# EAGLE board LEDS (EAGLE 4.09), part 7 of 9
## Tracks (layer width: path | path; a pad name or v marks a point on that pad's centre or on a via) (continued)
N$X.2554  (via drill 0.2)  (1 unrouted) (continued)
  other vias: 80.3,19.86
N$X.2555  (via drill 0.2)  (1 unrouted)
  Bottom 0.2: 80.62,22.52 80.08,23.07 79.72,23.07
  other vias: 80.58,22.5
N$X.2556  (via drill 0.2)  (1 unrouted)
  Bottom 0.2: 80.62,25.09 80.08,25.64 79.72,25.64
  other vias: 80.58,25.07
N$X.2557  (via drill 0.2)  (1 unrouted)
  Bottom 0.2: 82.31,25.09 81.77,25.64 81.42,25.64
  other vias: 82.27,25.07
N$X.2558  (via drill 0.2)  (1 unrouted)
  Bottom 0.2: 82.25,22.52 81.7,23.07 81.35,23.07
  other vias: 82.24,22.48
N$X.2559  (via drill 0.2)  (1 unrouted)
  Bottom 0.2: 82.11,19.91 81.56,20.45 81.22,20.45
  other vias: 82.06,19.89
N$X.2560  (via drill 0.2)  (1 unrouted)
  Bottom 0.2: 83.99,19.93 83.44,20.47 83.09,20.47
  other vias: 83.94,19.91
N$X.2561  (via drill 0.2)  (1 unrouted)
  Bottom 0.2: 84.03,22.55 83.49,23.09 83.14,23.09
  other vias: 83.99,22.53
N$X.2562  (via drill 0.2)  (1 unrouted)
  Bottom 0.2: 84.03,25.09 83.49,25.64 83.14,25.64
  other vias: 83.99,25.07
N$X.2563  (via drill 0.2)  (1 unrouted)
  Bottom 0.2: 85.83,25.12 85.28,25.66 84.93,25.66
  other vias: 85.78,25.1
N$X.2564  (via drill 0.2)  (1 unrouted)
  Bottom 0.2: 85.83,22.52 85.28,23.07 84.93,23.07
  other vias: 85.78,22.5
N$X.2565  (via drill 0.2)  (1 unrouted)
  Bottom 0.2: 85.83,19.88 85.28,20.43 84.93,20.43
  other vias: 85.78,19.86
N$X.2566  (via drill 0.2)  (1 unrouted)
  Bottom 0.2: 101.57,22.52 101.03,23.07 100.67,23.07
  other vias: 101.53,22.5
N$X.2567  (via drill 0.2)  (1 unrouted)
  Bottom 0.2: 101.59,19.95 101.05,20.5 100.7,20.5
  other vias: 101.55,19.89
N$X.2568  (via drill 0.2)  (1 unrouted)
  Bottom 0.2: 99.89,19.88 99.35,20.43 99,20.43
  other vias: 99.85,19.86
N$X.2569  (via drill 0.2)  (1 unrouted)
  Bottom 0.2: 99.88,22.5 99.33,23.04 98.98,23.04
  other vias: 99.83,22.48
N$X.2570  (via drill 0.2)  (1 unrouted)
  Bottom 0.2: 99.78,25.14 99.23,25.68 98.89,25.68
  other vias: 99.73,25.12
N$X.2571  (via drill 0.2)  (1 unrouted)
  Bottom 0.2: 98.06,25.16 97.52,25.71 97.16,25.71
  other vias: 98.02,25.1
N$X.2572  (via drill 0.2)  (1 unrouted)
  Bottom 0.2: 98.08,22.5 97.54,23.04 97.19,23.04
  other vias: 98.04,22.48
N$X.2573  (via drill 0.2)  (1 unrouted)
  Bottom 0.2: 98.03,19.88 97.49,20.43 97.14,20.43
  other vias: 97.99,19.86
N$X.2574  (via drill 0.2)  (1 unrouted)
  Bottom 0.2: 96.34,19.88 95.8,20.43 95.44,20.43
  other vias: 96.3,19.86
N$X.2575  (via drill 0.2)  (1 unrouted)
  Bottom 0.2: 96.36,22.5 95.81,23.04 95.47,23.04
  other vias: 96.31,22.48
N$X.2576  (via drill 0.2)  (1 unrouted)
  Bottom 0.2: 96.36,25.12 95.81,25.66 95.47,25.66
  other vias: 96.31,25.1
N$X.2577  (via drill 0.2)  (1 unrouted)
  Bottom 0.2: 94.61,25.07 94.07,25.62 93.72,25.62
  other vias: 94.57,25.05
N$X.2578  (via drill 0.2)  (1 unrouted)
  Bottom 0.2: 94.66,22.45 94.12,23 93.77,23
  other vias: 94.62,22.43
N$X.2579  (via drill 0.2)  (1 unrouted)
  Bottom 0.2: 94.69,19.84 94.14,20.38 93.79,20.38
  other vias: 94.56,19.88
N$X.2580  (via drill 0.2)  (1 unrouted)
  Bottom 0.2: 92.97,19.91 92.42,20.45 92.07,20.45
  other vias: 92.92,19.89
N$X.2581  (via drill 0.2)  (1 unrouted)
  Bottom 0.2: 92.97,22.5 92.42,23.04 92.07,23.04
  other vias: 92.92,22.48
N$X.2582  (via drill 0.2)  (1 unrouted)
  Bottom 0.2: 92.94,25.07 92.39,25.62 92.05,25.62
  other vias: 92.89,25.05
N$X.2583  (via drill 0.2)  (1 unrouted)
  Bottom 0.2: 91.15,25.09 90.61,25.64 90.25,25.64
  other vias: 91.11,25.07
N$X.2584  (via drill 0.2)  (1 unrouted)
  Bottom 0.2: 91.11,22.43 90.56,22.98 90.21,22.98
  other vias: 91.04,22.45
N$X.2585  (via drill 0.2)  (1 unrouted)
  Bottom 0.2: 91.15,19.88 90.61,20.43 90.25,20.43
  other vias: 91.11,19.86
N$X.2586  (via drill 0.2)  (1 unrouted)
  Bottom 0.2: 89.34,25.12 88.8,25.66 88.44,25.66
  other vias: 89.3,25.1
N$X.2587
  Bottom 0.2: 88.8,25.66 88.44,25.66
N$X.2588  (via drill 0.2)  (1 unrouted)
  Bottom 0.2: 87.59,25.05 87.05,25.59 86.7,25.59
  other vias: 87.53,25.09
N$X.2589  (via drill 0.2)  (1 unrouted)
  Bottom 0.2: 87.57,22.45 87.03,23 86.67,23
  other vias: 87.48,22.47
N$X.2590  (via drill 0.2)  (1 unrouted)
  Bottom 0.2: 89.3,22.48 88.75,23.02 88.4,23.02
  other vias: 89.25,22.46
N$X.2591  (via drill 0.2)  (1 unrouted)
  Bottom 0.2: 89.39,19.84 88.84,20.38 88.49,20.38
  other vias: 89.3,19.88
N$X.2592  (via drill 0.2)  (1 unrouted)
  Bottom 0.2: 87.62,19.91 87.08,20.45 86.72,20.45
  other vias: 87.58,19.89
N$X.2596  (via drill 0.2)  (1 unrouted)
  Bottom 0.2: 112.11,43.66 111.56,44.2 111.21,44.2
  other vias: 112.02,43.66
N$X.2597  (via drill 0.2)  (1 unrouted)
  Bottom 0.2: 112.02,41.13 111.47,41.68 111.12,41.68
  other vias: 111.97,41.11
N$X.2598  (via drill 0.2)  (1 unrouted)
  Bottom 0.2: 5.32,48.8 4.77,49.34 4.42,49.34
  other vias: 5.28,48.74
N$X.2599  (via drill 0.2)  (1 unrouted)
  Bottom 0.2: 7.06,48.8 6.52,49.34 6.17,49.34
  other vias: 7.02,48.75
N$X.2600  (via drill 0.2)  (1 unrouted)
  Bottom 0.2: 8.9,48.8 8.36,49.34 8.01,49.34
  other vias: 8.86,48.78
N$X.2601  (via drill 0.2)  (1 unrouted)
  Bottom 0.2: 10.67,48.75 10.12,49.3 9.77,49.3
  other vias: 10.62,48.73
N$X.2602  (via drill 0.2)  (1 unrouted)
  Bottom 0.2: 12.44,48.78 11.89,49.32 11.54,49.32
  other vias: 12.39,48.76
N$X.2603  (via drill 0.2)  (1 unrouted)
  Bottom 0.2: 14.18,48.82 13.63,49.37 13.29,49.37
  other vias: 14.13,48.8
N$X.2604  (via drill 0.2)  (1 unrouted)
  Bottom 0.2: 15.95,48.75 15.4,49.3 15.05,49.3
  other vias: 16.02,48.72
N$X.2605  (via drill 0.2)  (1 unrouted)
  Bottom 0.2: 17.59,48.75 17.05,49.3 16.7,49.3
  other vias: 17.81,48.76
N$X.2606  (via drill 0.2)  (1 unrouted)
  Bottom 0.2: 19.38,48.85 18.84,49.39 18.49,49.39
  other vias: 19.61,48.77
N$X.2607  (via drill 0.2)  (1 unrouted)
  Bottom 0.2: 21.06,48.78 20.52,49.32 20.17,49.32
  other vias: 21.41,48.76
N$X.2608  (via drill 0.2)  (1 unrouted)
  Bottom 0.2: 21.08,51.35 20.54,51.89 20.19,51.89
  other vias: 21.37,51.29
N$X.2609  (via drill 0.2)  (1 unrouted)
  Bottom 0.2: 19.34,51.35 18.79,51.89 18.45,51.89
  other vias: 19.57,51.29
N$X.2610  (via drill 0.2)  (1 unrouted)
  Bottom 0.2: 17.59,51.42 17.05,51.96 16.7,51.96
  other vias: 17.77,51.32
N$X.2611  (via drill 0.2)  (1 unrouted)
  Bottom 0.2: 15.83,51.39 15.29,51.94 14.94,51.94
  other vias: 16.03,51.31
N$X.2612  (via drill 0.2)  (1 unrouted)
  Bottom 0.2: 14.13,51.39 13.59,51.94 13.24,51.94
  other vias: 14.09,51.37
N$X.2613  (via drill 0.2)  (1 unrouted)
  Bottom 0.2: 12.34,51.42 11.79,51.96 11.45,51.96
  other vias: 12.29,51.4
N$X.2614  (via drill 0.2)  (1 unrouted)
  Bottom 0.2: 10.55,51.44 10.01,51.98 9.66,51.98
  other vias: 10.53,51.38
N$X.2615  (via drill 0.2)  (1 unrouted)
  Bottom 0.2: 8.86,51.32 8.31,51.87 7.96,51.87
  other vias: 8.81,51.3
N$X.2616  (via drill 0.2)  (1 unrouted)
  Bottom 0.2: 7.08,51.42 6.54,51.96 6.19,51.96
  other vias: 7.03,51.33
N$X.2617  (via drill 0.2)  (1 unrouted)
  Bottom 0.2: 5.26,51.37 4.72,51.92 4.51,51.94
  other vias: 5.24,51.31
N$X.2618  (via drill 0.2)  (1 unrouted)
  Bottom 0.2: 3.55,51.37 3.01,51.92 2.66,51.92
  other vias: 3.47,51.3
N$X.2619  (via drill 0.2)  (1 unrouted)
  Bottom 0.2: 3.58,53.96 3.03,54.51 2.68,54.51
  other vias: 3.52,53.91
N$X.2620  (via drill 0.2)  (1 unrouted)
  Bottom 0.2: 5.34,53.92 4.79,54.46 4.44,54.46
  other vias: 5.29,53.9
N$X.2621  (via drill 0.2)  (1 unrouted)
  Bottom 0.2: 7.04,53.96 6.5,54.51 6.14,54.51
  other vias: 7.05,53.92
N$X.2622  (via drill 0.2)  (1 unrouted)
  Bottom 0.2: 8.78,53.97 8.23,54.51 8.01,54.55
  other vias: 8.79,53.92
N$X.2623  (via drill 0.2)  (1 unrouted)
  Bottom 0.2: 10.6,53.96 10.06,54.51 9.71,54.51
  other vias: 10.57,53.89
N$X.2624  (via drill 0.2)  (1 unrouted)
  Bottom 0.2: 12.39,53.94 11.85,54.49 11.5,54.49
  other vias: 12.35,53.92
N$X.2625  (via drill 0.2)  (1 unrouted)
  Bottom 0.2: 14.13,53.96 13.59,54.51 13.24,54.51
  other vias: 14.09,53.94
N$X.2626  (via drill 0.2)  (1 unrouted)
  Bottom 0.2: 15.73,53.92 15.19,54.47 14.98,54.51
  other vias: 15.85,53.92
N$X.2627  (via drill 0.2)  (1 unrouted)
  Bottom 0.2: 17.55,54.01 17,54.55 16.65,54.55
  other vias: 17.7,53.89
N$X.2628  (via drill 0.2)  (1 unrouted)
  Bottom 0.2: 19.38,53.96 18.84,54.51 18.49,54.51
  other vias: 19.45,53.87
N$X.2629  (via drill 0.2)  (1 unrouted)
  Bottom 0.2: 21.38,53.87 20.52,54.55 20.17,54.55
  other vias: 21.35,53.88
N$X.2630  (via drill 0.2)  (1 unrouted)
  Bottom 0.2: 21.11,56.67 20.56,57.22 20.21,57.22
  other vias: 21.06,56.65
N$X.2631  (via drill 0.2)  (1 unrouted)
  Bottom 0.2: 19.46,56.72 18.95,57.26 18.61,57.26
  other vias: 19.56,56.63
N$X.2632  (via drill 0.2)  (1 unrouted)
  Bottom 0.2: 17.7,56.8 17.21,57.26 16.86,57.26
  other vias: 17.84,56.64
N$X.2633  (via drill 0.2)  (1 unrouted)
  Bottom 0.2: 15.97,56.72 15.43,57.26 15.08,57.26
  other vias: 16.05,56.62
N$X.2634  (via drill 0.2)  (1 unrouted)
  Bottom 0.2: 14.09,56.76 13.54,57.31 13.19,57.31
  other vias: 14.08,56.66
N$X.2635  (via drill 0.2)  (1 unrouted)
  Bottom 0.2: 12.32,56.72 11.78,57.26 11.43,57.26
  other vias: 12.42,56.68
N$X.2636  (via drill 0.2)  (1 unrouted)
  Bottom 0.2: 10.53,56.67 9.99,57.22 9.63,57.22
  other vias: 10.6,56.64
N$X.2637  (via drill 0.2)  (1 unrouted)
  Bottom 0.2: 8.74,56.69 8.2,57.24 7.84,57.24
  other vias: 8.77,56.63
N$X.2638  (via drill 0.2)  (1 unrouted)
  Bottom 0.2: 7,56.67 6.45,57.22 6.1,57.22
  other vias: 7.04,56.64
N$X.2639  (via drill 0.2)  (1 unrouted)
  Bottom 0.2: 5.25,56.65 4.71,57.19 4.35,57.19
  other vias: 5.21,56.63
N$X.2640  (via drill 0.2)  (1 unrouted)
  Bottom 0.2: 3.44,56.65 2.89,57.19 2.54,57.19
  other vias: 3.39,56.63
N$X.2641  (via drill 0.2)  (1 unrouted)
  Bottom 0.2: 21.2,59.43 20.65,59.97 20.3,59.97
  other vias: 21.39,59.35
N$X.2642  (via drill 0.2)  (1 unrouted)
  Bottom 0.2: 23.17,59.43 22.4,59.95 22.05,59.95
  other vias: 23.25,59.37
N$X.2643  (via drill 0.2)  (1 unrouted)
  Bottom 0.2: 22.95,56.65 22.4,57.19 22.05,57.19
  other vias: 22.9,56.63
N$X.2644  (via drill 0.2)  (1 unrouted)
  Bottom 0.2: 23.2,53.92 22.26,54.53 21.91,54.53
  other vias: 23.24,53.9
N$X.2645  (via drill 0.2)  (1 unrouted)
  Bottom 0.2: 22.86,51.39 22.31,51.94 21.96,51.94
  other vias: 22.81,51.37
N$X.2646  (via drill 0.2)  (1 unrouted)
  Bottom 0.2: 23.16,48.74 22.33,49.37 21.98,49.37
  other vias: 23.18,48.73
N$X.2647  (via drill 0.2)  (1 unrouted)
  Bottom 0.2: 24.95,48.74 24.1,49.39 23.75,49.39
  other vias: 24.97,48.73
N$X.2648  (via drill 0.2)  (1 unrouted)
  Bottom 0.2: 24.89,51.33 24.07,51.96 23.72,51.96
  other vias: 24.94,51.27
N$X.2649  (via drill 0.2)  (1 unrouted)
  Bottom 0.2: 25.06,53.88 24.05,54.51 23.7,54.51
  other vias: 25.03,53.91
N$X.2650  (via drill 0.2)  (1 unrouted)
  Bottom 0.2: 24.95,56.61 24.41,57.16 23.79,57.19
  other vias: 24.97,56.64
N$X.2651  (via drill 0.2)  (1 unrouted)
  Bottom 0.2: 24.98,59.39 24.12,59.97 23.77,59.97
  other vias: 25.01,59.39
N$X.2652  (via drill 0.2)  (1 unrouted)
  Bottom 0.2: 26.74,59.39 25.89,59.97 25.54,59.97
  other vias: 26.77,59.39
N$X.2653  (via drill 0.2)  (1 unrouted)
  Bottom 0.2: 26.79,56.64 25.95,57.24 25.61,57.24
  other vias: 26.77,56.65
N$X.2654  (via drill 0.2)  (1 unrouted)
  Bottom 0.2: 26.77,53.93 25.77,54.53 25.42,54.53
  other vias: 26.81,53.92
N$X.2655  (via drill 0.2)  (1 unrouted)
  Bottom 0.2: 26.81,51.32 25.7,51.92 25.68,51.94
  other vias: 26.82,51.31
N$X.2656  (via drill 0.2)  (1 unrouted)
  Bottom 0.2: 26.74,48.71 25.77,49.34 25.42,49.34
  other vias: 26.76,48.73
N$X.2657  (via drill 0.2)  (1 unrouted)
  Bottom 0.2: 28.57,48.74 27.56,49.34 27.21,49.34
  other vias: 28.59,48.74
N$X.2658  (via drill 0.2)  (2 unrouted)
  Bottom 0.2: 27.56,51.94 27.21,51.94 | 28.55,51.23 27.74,52.04 27.54,52.04
  other vias: 28.61,51.29
N$X.2659  (via drill 0.2)  (1 unrouted)
  Bottom 0.2: 28.66,53.9 27.54,54.51 27.19,54.51
  other vias: 28.62,53.91
N$X.2660  (via drill 0.2)  (1 unrouted)
  Bottom 0.2: 28.55,56.63 27.9,57.29 27.72,57.29
  other vias: 28.58,56.63
N$X.2661  (via drill 0.2)  (1 unrouted)
  Bottom 0.2: 28.52,59.39 27.61,59.97 27.26,59.97
  other vias: 28.59,59.36
N$X.2662  (via drill 0.2)  (1 unrouted)
  Bottom 0.2: 30.36,59.38 29.82,59.93 29.05,59.99
  other vias: 30.38,59.36
N$X.2663  (via drill 0.2)  (1 unrouted)
  Bottom 0.2: v30.4,56.63 29.81,57.22 29.52,57.22
N$X.2664  (via drill 0.2)  (2 unrouted)
  Bottom 0.2: 29.33,54.53 28.98,54.53 | 30.35,53.97 29.67,54.65 29.34,54.65
  other vias: 30.38,53.92
N$X.2665  (via drill 0.2)  (2 unrouted)
  Bottom 0.2: 29.36,51.94 29,51.94 | 30.4,51.3 29.8,51.89 29.43,51.89
  other vias: 30.43,51.34
N$X.2666  (via drill 0.2)  (1 unrouted)
  Bottom 0.2: 30.3,48.71 29.31,49.34 28.96,49.34
  other vias: 30.24,48.76
N$X.2667  (via drill 0.2)  (1 unrouted)
  Bottom 0.2: 32.18,48.75 31.47,49.45 31.17,49.45
  other vias: 32.21,48.76
N$X.2668  (via drill 0.2)  (1 unrouted)
  Bottom 0.2: 32.24,51.3 31.63,51.91 31.17,51.91
  other vias: 32.21,51.28
N$X.2669  (via drill 0.2)  (1 unrouted)
  Bottom 0.2: 32.24,53.78 31.45,54.57 31.28,54.57
  other vias: 32.21,53.92
N$X.2670  (via drill 0.2)  (1 unrouted)
  Bottom 0.2: 32.15,56.63 31.43,57.35 31.19,57.35
  other vias: 32.17,56.65
N$X.2671  (via drill 0.2)  (1 unrouted)
  Bottom 0.2: 32.13,59.42 31.58,59.97 30.79,59.99
  other vias: 32.19,59.36
N$X.2672  (via drill 0.2)  (1 unrouted)
  Bottom 0.2: 33.98,59.33 33.44,59.88 33.06,59.88
  other vias: 33.98,59.36
N$X.2673  (via drill 0.2)  (1 unrouted)
  Bottom 0.2: 34,56.63 33.36,57.27 32.97,57.27
  other vias: 34.03,56.63
N$X.2674  (via drill 0.2)  (1 unrouted)
  Bottom 0.2: 34.13,53.93 33.56,54.5 32.94,54.5
  other vias: 34.06,53.95
N$X.2675  (via drill 0.2)  (1 unrouted)
  Bottom 0.2: 34,51.27 33.49,51.78 32.97,51.78
  other vias: 33.98,51.33
N$X.2676  (via drill 0.2)  (1 unrouted)
  Bottom 0.2: 33.95,48.75 33.34,49.37 33.12,49.37
  other vias: 34.02,48.76
N$X.2677  (via drill 0.2)  (1 unrouted)
  Bottom 0.2: 35.82,48.73 35.18,49.37 34.48,49.37
  other vias: 35.78,48.76
N$X.2678  (via drill 0.2)  (1 unrouted)
  Bottom 0.2: 35.77,51.27 35.05,52 34.68,52
  other vias: 35.79,51.33
N$X.2679  (via drill 0.2)  (1 unrouted)
  Bottom 0.2: 35.84,53.89 35.25,54.48 34.83,54.48
  other vias: 35.8,53.94
N$X.2680  (via drill 0.2)  (1 unrouted)
  Bottom 0.2: 35.8,56.67 35.27,57.2 34.9,57.2
  other vias: 35.81,56.65
N$X.2681  (via drill 0.2)  (1 unrouted)
  Bottom 0.2: 35.75,59.34 35.2,59.88 34.81,59.95
  other vias: 35.74,59.36
N$X.2682  (via drill 0.2)  (1 unrouted)
  Bottom 0.2: 37.6,59.41 37.06,59.95 36.44,59.95
  other vias: 37.65,59.36
N$X.2683  (via drill 0.2)  (1 unrouted)
  Bottom 0.2: v37.62,56.61 37.03,57.2 36.63,57.2
N$X.2684  (via drill 0.2)  (1 unrouted)
  Bottom 0.2: 37.69,53.93 37.03,54.59 36.43,54.59
  other vias: 37.64,53.9
N$X.2685  (via drill 0.2)  (1 unrouted)
  Bottom 0.2: v37.64,51.34 36.98,52 36.52,52
N$X.2686  (via drill 0.2)  (1 unrouted)
  Bottom 0.2: 37.64,48.77 37,49.41 36.56,49.41
  other vias: 37.64,48.75
N$X.2687  (via drill 0.2)  (1 unrouted)
  Bottom 0.2: 39.46,48.73 38.87,49.32 38.34,49.32
  other vias: 39.45,48.73
N$X.2688  (via drill 0.2)  (1 unrouted)
  Bottom 0.2: 39.4,51.27 38.69,51.98 38.25,51.98
  other vias: 39.38,51.33
N$X.2689  (via drill 0.2)  (1 unrouted)
  Bottom 0.2: 39.42,53.91 38.89,54.44 38.39,54.44
  other vias: 39.43,53.9
N$X.2690  (via drill 0.2)  (1 unrouted)
  Bottom 0.2: 39.44,56.67 38.85,57.27 38.52,57.27
  other vias: 39.39,56.65
N$X.2691  (via drill 0.2)  (1 unrouted)
  Bottom 0.2: 39.44,59.31 38.89,59.86 38.41,59.94
  other vias: 39.46,59.34
N$X.2753
  Bottom 0.2: 60.63,51.87 60.28,51.87
N$X.2755
  Bottom 0.2: 62.38,54.53 62.03,54.53
N$X.2756
  Bottom 0.2: 62.34,51.89 61.98,51.89
N$X.2757
  Bottom 0.2: 62.45,49.25 62.09,49.25
N$X.2758
  Bottom 0.2: 64.14,49.34 63.8,49.34
N$X.2759
  Bottom 0.2: 64.12,51.92 63.77,51.92
N$X.2760
  Bottom 0.2: 64.14,54.58 63.8,54.58
N$X.2765
  Bottom 0.2: 65.94,54.53 65.58,54.53
N$X.2766
  Bottom 0.2: 65.96,51.94 65.61,51.94
N$X.2767
  Bottom 0.2: 65.96,49.37 65.61,49.37
N$X.2768  (via drill 0.2)  (1 unrouted)
  Bottom 0.2: 68.25,48.8 67.7,49.34 67.36,49.34
  other vias: 68.2,48.78
N$X.2769  (via drill 0.2)  (1 unrouted)
  Bottom 0.2: 68.27,51.37 67.72,51.92 67.38,51.92
  other vias: 68.22,51.35
N$X.2770  (via drill 0.2)  (1 unrouted)
  Bottom 0.2: 68.2,53.96 67.66,54.51 67.3,54.51
  other vias: 68.16,53.94
N$X.2771  (via drill 0.2)  (1 unrouted)
  Bottom 0.2: 68.45,56.63 67.91,57.17 67.56,57.17
  other vias: 68.41,56.61
N$X.2772  (via drill 0.2)  (1 unrouted)
  Bottom 0.2: 68.43,59.38 67.89,59.92 67.53,59.92
  other vias: 68.39,59.36
N$X.2773  (via drill 0.2)  (1 unrouted)
  Bottom 0.2: 70.29,59.36 69.75,59.9 69.39,59.9
  other vias: 70.25,59.34
N$X.2774  (via drill 0.2)  (1 unrouted)
  Bottom 0.2: 70.17,56.69 69.63,57.24 69.28,57.24
  other vias: 70.13,56.67
N$X.2775  (via drill 0.2)  (1 unrouted)
  Bottom 0.2: 70.04,53.99 69.5,54.53 69.14,54.53
  other vias: 70,53.97
N$X.2776  (via drill 0.2)  (1 unrouted)
  Bottom 0.2: 70.08,51.35 69.54,51.89 69.19,51.89
  other vias: 70.04,51.33
N$X.2777  (via drill 0.2)  (1 unrouted)
  Bottom 0.2: 70.08,48.78 69.54,49.32 69.19,49.32
  other vias: 70.04,48.76
N$X.2778  (via drill 0.2)  (1 unrouted)
  Bottom 0.2: 71.8,48.8 71.26,49.34 70.91,49.34
  other vias: 71.76,48.78
N$X.2779  (via drill 0.2)  (1 unrouted)
  Bottom 0.2: 71.76,51.32 71.22,51.87 70.86,51.87
  other vias: 71.72,51.3
N$X.2780  (via drill 0.2)  (1 unrouted)
  Bottom 0.2: 71.8,53.96 71.26,54.51 70.91,54.51
  other vias: 71.76,53.94
N$X.2781  (via drill 0.2)  (1 unrouted)
  Bottom 0.2: 71.97,56.65 71.42,57.19 71.07,57.19
  other vias: 71.92,56.63
N$X.2782  (via drill 0.2)  (1 unrouted)
  Bottom 0.2: 71.99,59.4 71.44,59.95 71.09,59.95
  other vias: 71.94,59.38
N$X.2783  (via drill 0.2)  (1 unrouted)
  Bottom 0.2: 73.75,59.43 73.21,59.97 72.86,59.97
  other vias: 73.71,59.39
N$X.2784  (via drill 0.2)  (1 unrouted)
  Bottom 0.2: 73.75,56.65 73.21,57.19 72.86,57.19
  other vias: 73.71,56.63
N$X.2785  (via drill 0.2)  (1 unrouted)
  Bottom 0.2: 73.59,53.89 73.05,54.44 72.7,54.44
  other vias: 73.55,53.87
N$X.2786  (via drill 0.2)  (1 unrouted)
  Bottom 0.2: 73.5,51.35 72.96,51.89 72.61,51.89
  other vias: 73.46,51.33
N$X.2787  (via drill 0.2)  (1 unrouted)
  Bottom 0.2: 73.55,48.82 73,49.37 72.66,49.37
  other vias: 73.5,48.78
N$X.2788  (via drill 0.2)  (1 unrouted)
  Bottom 0.2: 75.31,48.8 74.77,49.34 74.42,49.34
  other vias: 75.25,48.73
N$X.2789  (via drill 0.2)  (1 unrouted)
  Bottom 0.2: 75.27,51.42 74.72,51.96 74.38,51.96
  other vias: 75.22,51.4
N$X.2790  (via drill 0.2)  (1 unrouted)
  Bottom 0.2: 75.2,53.94 74.66,54.49 74.3,54.49
  other vias: 75.16,53.92
N$X.2791  (via drill 0.2)  (1 unrouted)
  Bottom 0.2: 75.41,56.67 74.86,57.22 74.52,57.22
  other vias: 75.36,56.65
N$X.2792  (via drill 0.2)  (1 unrouted)
  Bottom 0.2: 75.43,59.38 74.89,59.92 74.53,59.92
  other vias: 75.39,59.36
N$X.2793  (via drill 0.2)  (1 unrouted)
  Bottom 0.2: 77.2,59.38 76.66,59.92 76.3,59.92
  other vias: 77.16,59.36
N$X.2794  (via drill 0.2)  (1 unrouted)
  Bottom 0.2: 77.13,56.65 76.58,57.19 76.23,57.19
  other vias: 77.08,56.63
N$X.2795  (via drill 0.2)  (1 unrouted)
  Bottom 0.2: 77.04,54.03 76.5,54.58 76.14,54.58
  other vias: 77.02,53.93
N$X.2796  (via drill 0.2)  (1 unrouted)
  Bottom 0.2: 77.04,51.32 76.5,51.87 76.14,51.87
  other vias: 77,51.3
N$X.2797  (via drill 0.2)  (1 unrouted)
  Bottom 0.2: 76.97,48.8 76.42,49.34 76.08,49.34
  other vias: 76.92,48.78
N$X.2798  (via drill 0.2)  (1 unrouted)
  Bottom 0.2: 78.73,48.76 78.21,49.33 77.82,49.37
  other vias: 78.69,48.74
N$X.2799  (via drill 0.2)  (1 unrouted)
  Bottom 0.2: 80.45,48.91 79.91,49.46 79.56,49.46
  other vias: 80.41,48.83
N$X.2800  (via drill 0.2)  (1 unrouted)
  Bottom 0.2: 80.44,51.35 79.89,51.89 79.54,51.89
  other vias: 80.39,51.33
N$X.2801  (via drill 0.2)  (1 unrouted)
  Bottom 0.2: 78.66,51.37 78.12,51.92 77.77,51.92
  other vias: 78.62,51.35
N$X.2802  (via drill 0.2)  (1 unrouted)
  Bottom 0.2: 78.66,53.96 78.12,54.51 77.77,54.51
  other vias: 78.62,53.94
N$X.2803  (via drill 0.2)  (1 unrouted)
  Bottom 0.2: 80.41,54.01 79.86,54.55 79.52,54.55
  other vias: 80.36,53.99
N$X.2804  (via drill 0.2)  (1 unrouted)
  Bottom 0.2: 80.71,56.67 80.16,57.22 79.81,57.22
  other vias: 80.66,56.65
N$X.2805  (via drill 0.2)  (1 unrouted)
  Bottom 0.2: 78.85,56.72 78.3,57.26 77.95,57.26
  other vias: 78.8,56.7
N$X.2806  (via drill 0.2)  (1 unrouted)
  Bottom 0.2: 78.88,59.47 78.33,60.02 77.98,60.02
  other vias: 78.83,59.45
N$X.2807  (via drill 0.2)  (1 unrouted)
  Bottom 0.2: 80.66,59.47 80.12,60.02 79.77,60.02
  other vias: 80.62,59.45
N$X.2808  (via drill 0.2)  (1 unrouted)
  Bottom 0.2: 82.45,56.69 81.91,57.24 81.56,57.24
  other vias: 82.41,56.67
N$X.2809  (via drill 0.2)  (1 unrouted)
  Bottom 0.2: 82.27,53.99 81.72,54.53 81.38,54.53
  other vias: 82.22,53.97
N$X.2810  (via drill 0.2)  (1 unrouted)
  Bottom 0.2: 82.27,51.39 81.72,51.94 81.38,51.94
  other vias: 82.22,51.37
N$X.2811  (via drill 0.2)  (1 unrouted)
  Bottom 0.2: 82.27,48.8 81.72,49.34 81.38,49.34
  other vias: 82.22,48.78
N$X.2812  (via drill 0.2)  (1 unrouted)
  Bottom 0.2: 84.27,59.4 83.72,59.95 83.37,59.95
  other vias: 84.22,59.38
N$X.2813  (via drill 0.2)  (1 unrouted)
  Bottom 0.2: 84.22,56.67 83.67,57.22 83.33,57.22
  other vias: 84.17,56.65
N$X.2814  (via drill 0.2)  (1 unrouted)
  Bottom 0.2: 84.03,53.99 83.49,54.53 83.14,54.53
  other vias: 83.99,53.97
N$X.2815  (via drill 0.2)  (1 unrouted)
  Bottom 0.2: 84.06,51.37 83.52,51.92 83.16,51.92
  other vias: 84.02,51.35
N$X.2816  (via drill 0.2)  (1 unrouted)
  Bottom 0.2: 84.08,48.75 83.54,49.3 83.19,49.3
  other vias: 84.04,48.73
N$X.2817  (via drill 0.2)  (1 unrouted)
  Bottom 0.2: 85.8,48.75 85.26,49.3 84.91,49.3
  other vias: 85.76,48.73
N$X.2818  (via drill 0.2)  (1 unrouted)
  Bottom 0.2: 85.83,51.37 85.28,51.92 84.93,51.92
  other vias: 85.78,51.35
N$X.2819  (via drill 0.2)  (1 unrouted)
  Bottom 0.2: 85.8,53.96 85.26,54.51 84.91,54.51
  other vias: 85.76,53.94
N$X.2820  (via drill 0.2)  (1 unrouted)
  Bottom 0.2: 86.01,56.69 85.47,57.24 85.11,57.24
  other vias: 85.97,56.67
N$X.2821  (via drill 0.2)  (1 unrouted)
  Bottom 0.2: 86.03,59.4 85.49,59.95 85.14,59.95
  other vias: 85.99,59.38
N$X.2822  (via drill 0.2)  (1 unrouted)
  Bottom 0.2: 87.71,59.38 87.16,59.92 86.81,59.92
  other vias: 87.66,59.36
N$X.2823  (via drill 0.2)  (1 unrouted)
  Bottom 0.2: 87.78,56.67 87.23,57.22 86.89,57.22
  other vias: 87.73,56.65
N$X.2824  (via drill 0.2)  (1 unrouted)
  Bottom 0.2: 87.59,53.96 87.05,54.51 86.7,54.51
  other vias: 87.55,53.94
N$X.2825  (via drill 0.2)  (1 unrouted)
  Bottom 0.2: 87.59,51.37 87.05,51.92 86.7,51.92
  other vias: 87.55,51.35
N$X.2826  (via drill 0.2)  (1 unrouted)
  Bottom 0.2: 87.59,48.8 87.05,49.34 86.7,49.34
  other vias: 87.55,48.78
N$X.2827  (via drill 0.2)  (1 unrouted)
  Bottom 0.2: 89.25,48.82 88.7,49.37 88.35,49.37
  other vias: 89.2,48.8
N$X.2828  (via drill 0.2)  (1 unrouted)
  Bottom 0.2: 89.31,51.37 88.77,51.92 88.42,51.92
  other vias: 89.27,51.35
N$X.2829  (via drill 0.2)  (1 unrouted)
  Bottom 0.2: 89.36,53.92 88.81,54.46 88.47,54.46
  other vias: 89.31,53.9
N$X.2830  (via drill 0.2)  (1 unrouted)
  Bottom 0.2: 89.45,56.69 88.91,57.24 88.56,57.24
  other vias: 89.41,56.67
N$X.2831  (via drill 0.2)  (1 unrouted)
  Bottom 0.2: 89.41,59.43 88.86,59.97 88.52,59.97
  other vias: 89.36,59.41
N$X.2832  (via drill 0.2)  (1 unrouted)
  Bottom 0.2: 91.2,59.43 90.66,59.97 90.3,59.97
  other vias: 91.16,59.41
N$X.2833  (via drill 0.2)  (1 unrouted)
  Bottom 0.2: 91.15,56.69 90.61,57.24 90.25,57.24
  other vias: 91.11,56.67
N$X.2834  (via drill 0.2)  (1 unrouted)
  Bottom 0.2: 90.97,54.01 90.42,54.55 90.08,54.55
  other vias: 90.92,53.99
N$X.2835  (via drill 0.2)  (1 unrouted)
  Bottom 0.2: 91.03,51.39 90.49,51.94 90.14,51.94
  other vias: 90.99,51.37
N$X.2836  (via drill 0.2)  (1 unrouted)
  Bottom 0.2: 91.11,48.71 90.56,49.25 90.21,49.25
  other vias: 91.06,48.69
N$X.2837  (via drill 0.2)  (1 unrouted)
  Bottom 0.2: v92.83,48.66 92.28,49.21 91.93,49.21
N$X.2838  (via drill 0.2)  (1 unrouted)
  Bottom 0.2: 92.92,51.46 92.38,52.01 92.03,52.01
  other vias: 92.88,51.44
N$X.2839  (via drill 0.2)  (1 unrouted)
  Bottom 0.2: 92.92,53.99 92.38,54.53 92.03,54.53
  other vias: 92.88,53.97
N$X.2840  (via drill 0.2)  (1 unrouted)
  Bottom 0.2: 92.97,56.69 92.42,57.24 92.07,57.24
  other vias: 92.92,56.67
N$X.2841  (via drill 0.2)  (1 unrouted)
  Bottom 0.2: 93.03,59.4 92.49,59.95 92.14,59.95
  other vias: 92.99,59.38
N$X.2842  (via drill 0.2)  (1 unrouted)
  Bottom 0.2: 94.73,59.43 94.19,59.97 93.83,59.97
  other vias: 94.69,59.41
N$X.2843  (via drill 0.2)  (1 unrouted)
  Bottom 0.2: 94.8,56.67 94.25,57.22 93.91,57.22
  other vias: 94.75,56.65
N$X.2844  (via drill 0.2)  (1 unrouted)
  Bottom 0.2: 94.73,53.96 94.19,54.51 93.83,54.51
  other vias: 94.69,53.94
N$X.2845  (via drill 0.2)  (1 unrouted)
  Bottom 0.2: 94.71,51.39 94.16,51.94 93.81,51.94
  other vias: 94.66,51.37
N$X.2846  (via drill 0.2)  (1 unrouted)
  Bottom 0.2: 94.55,48.73 94,49.28 93.66,49.28
  other vias: 94.5,48.71
N$X.2847  (via drill 0.2)  (1 unrouted)
  Bottom 0.2: 96.31,48.78 95.77,49.32 95.42,49.32
  other vias: 96.27,48.76
N$X.2848  (via drill 0.2)  (1 unrouted)
  Bottom 0.2: 96.47,51.39 95.93,51.94 95.58,51.94
  other vias: 96.43,51.37
N$X.2849  (via drill 0.2)  (1 unrouted)
  Bottom 0.2: 96.45,53.99 95.91,54.53 95.56,54.53
  other vias: 96.41,53.97
N$X.2850  (via drill 0.2)  (1 unrouted)
  Bottom 0.2: 96.45,56.69 95.91,57.24 95.56,57.24
  other vias: 96.41,56.67
N$X.2851  (via drill 0.2)  (1 unrouted)
  Bottom 0.2: 96.45,59.45 95.91,59.99 95.56,59.99
  other vias: 96.41,59.43
N$X.2852  (via drill 0.2)  (1 unrouted)
  Bottom 0.2: 98.22,59.43 97.67,59.97 97.33,59.97
  other vias: 98.17,59.41
N$X.2853  (via drill 0.2)  (1 unrouted)
  Bottom 0.2: 98.22,56.65 97.67,57.19 97.33,57.19
  other vias: 98.17,56.63
N$X.2854  (via drill 0.2)  (1 unrouted)
  Bottom 0.2: 98.27,53.96 97.72,54.51 97.37,54.51
  other vias: 98.22,53.94
N$X.2855  (via drill 0.2)  (1 unrouted)
  Bottom 0.2: 98.19,51.32 97.65,51.87 97.3,51.87
  other vias: 98.15,51.3
N$X.2856  (via drill 0.2)  (1 unrouted)
  Bottom 0.2: 98.03,48.8 97.49,49.34 97.14,49.34
  other vias: 97.99,48.78
N$X.2857  (via drill 0.2)  (1 unrouted)
  Bottom 0.2: 99.76,48.69 99.22,49.23 98.86,49.23
  other vias: 99.72,48.67
N$X.2858  (via drill 0.2)  (1 unrouted)
  Bottom 0.2: 100.03,51.39 99.49,51.94 99.14,51.94
  other vias: 99.99,51.29
N$X.2859  (via drill 0.2)  (1 unrouted)
  Bottom 0.2: 100.01,54.01 99.47,54.55 99.11,54.55
  other vias: 99.97,53.92
N$X.2860  (via drill 0.2)  (1 unrouted)
  Bottom 0.2: 100.03,56.65 99.49,57.19 99.14,57.19
  other vias: 99.99,56.63
N$X.2861  (via drill 0.2)  (1 unrouted)
  Bottom 0.2: 100.01,59.43 99.47,59.97 99.11,59.97
  other vias: 99.97,59.41
N$X.2862  (via drill 0.2)  (1 unrouted)
  Bottom 0.2: 101.72,56.68 101.18,57.23 100.83,57.23
  other vias: 101.68,56.66
N$X.2863  (via drill 0.2)  (1 unrouted)
  Bottom 0.2: 101.7,53.92 101.16,54.47 100.81,54.47
  other vias: 101.66,53.9
N$X.2864  (via drill 0.2)  (1 unrouted)
  Bottom 0.2: 101.7,51.36 101.16,51.91 100.81,51.91
  other vias: 101.66,51.34
N$X.2865  (via drill 0.2)  (1 unrouted)
  Bottom 0.2: 101.55,48.76 101,49.31 100.66,49.31
  other vias: 101.5,48.74
N$X.2866  (via drill 0.2)  (1 unrouted)
  Bottom 0.2: 103.28,48.74 102.73,49.28 102.39,49.28
  other vias: 103.23,48.72
N$X.2867  (via drill 0.2)  (1 unrouted)
  Bottom 0.2: 103.44,51.39 102.89,51.93 102.54,51.93
  other vias: 103.37,51.31
N$X.2868  (via drill 0.2)  (1 unrouted)
  Bottom 0.2: 103.41,53.95 102.86,54.49 102.52,54.49
  other vias: 103.36,53.93
N$X.2869  (via drill 0.2)  (1 unrouted)
  Bottom 0.2: 103.41,56.7 102.86,57.25 102.52,57.25
  other vias: 103.36,56.68
N$X.2870  (via drill 0.2)  (1 unrouted)
  Bottom 0.2: 103.41,59.37 102.86,59.92 102.52,59.92
  other vias: 103.36,59.35
N$X.2871  (via drill 0.2)  (1 unrouted)
  Bottom 0.2: 105.23,59.4 104.69,59.94 104.33,59.94
  other vias: 105.19,59.38
N$X.2872  (via drill 0.2)  (1 unrouted)
  Bottom 0.2: 105.2,56.68 104.66,57.23 104.31,57.23
  other vias: 105.16,56.66
N$X.2873  (via drill 0.2)  (1 unrouted)
  Bottom 0.2: 105.19,54.01 104.64,54.56 104.29,54.56
  other vias: 105.14,53.99
N$X.2874  (via drill 0.2)  (1 unrouted)
  Bottom 0.2: 105.08,51.39 104.53,51.93 104.18,51.93
  other vias: 105.03,51.37
N$X.2875  (via drill 0.2)  (1 unrouted)
  Bottom 0.2: 105.01,48.76 104.47,49.31 104.11,49.31
  other vias: 104.97,48.74
N$X.2876  (via drill 0.2)  (1 unrouted)
  Bottom 0.2: 106.76,48.8 106.22,49.35 105.86,49.35
  other vias: 106.72,48.78
N$X.2877  (via drill 0.2)  (1 unrouted)
  Bottom 0.2: 106.78,51.41 106.23,51.95 105.89,51.95
  other vias: 106.73,51.39
N$X.2878  (via drill 0.2)  (1 unrouted)
  Bottom 0.2: 106.87,53.99 106.33,54.54 105.97,54.54
  other vias: 106.83,53.97
N$X.2879  (via drill 0.2)  (1 unrouted)
  Bottom 0.2: 106.89,56.73 106.34,57.27 106,57.27
  other vias: 106.84,56.71
N$X.2880  (via drill 0.2)  (1 unrouted)
  Bottom 0.2: 106.91,59.4 106.37,59.94 106.02,59.94
  other vias: 106.87,59.38
N$X.2881  (via drill 0.2)  (1 unrouted)
  Bottom 0.2: 108.66,59.31 108.12,59.85 107.77,59.85
  other vias: 108.62,59.35
N$X.2882  (via drill 0.2)  (1 unrouted)
  Bottom 0.2: 110.46,59.4 109.91,59.94 109.56,59.94
  other vias: 110.41,59.38
N$X.2883  (via drill 0.2)  (1 unrouted)
  Bottom 0.2: 112.23,59.37 111.69,59.92 111.33,59.92
  other vias: 112.19,59.35
N$X.2884  (via drill 0.2)  (1 unrouted)
  Bottom 0.2: 112.14,56.73 111.6,57.27 111.25,57.27
  other vias: 112.1,56.71
N$X.2885  (via drill 0.2)  (1 unrouted)
  Bottom 0.2: 110.41,56.68 109.87,57.23 109.52,57.23
  other vias: 110.37,56.66
N$X.2886  (via drill 0.2)  (1 unrouted)
  Bottom 0.2: 108.66,56.7 108.12,57.25 107.77,57.25
  other vias: 108.62,56.68
N$X.2887  (via drill 0.2)  (1 unrouted)
  Bottom 0.2: 108.75,53.92 108.2,54.47 107.86,54.47
  other vias: 108.7,53.9
N$X.2888  (via drill 0.2)  (1 unrouted)
  Bottom 0.2: 110.39,53.92 109.85,54.47 109.5,54.47
  other vias: 110.35,53.9
N$X.2889  (via drill 0.2)  (1 unrouted)
  Bottom 0.2: 112.23,53.9 111.69,54.45 111.33,54.45
  other vias: 112.19,53.88
N$X.2890  (via drill 0.2)  (1 unrouted)
  Bottom 0.2: 111.97,51.37 111.47,51.93 111.11,51.93
  other vias: 111.92,51.35
N$X.2891  (via drill 0.2)  (1 unrouted)
  Bottom 0.2: 110.19,51.34 109.65,51.89 109.3,51.89
  other vias: 110.15,51.32
N$X.2892  (via drill 0.2)  (1 unrouted)
  Bottom 0.2: 108.47,51.34 107.92,51.89 107.57,51.89
  other vias: 108.42,51.32
N$X.2893  (via drill 0.2)  (1 unrouted)
  Bottom 0.2: 108.51,48.83 107.97,49.37 107.61,49.37
  other vias: 108.47,48.77
N$X.2894  (via drill 0.2)  (1 unrouted)
  Bottom 0.2: 110.22,48.78 109.67,49.33 109.33,49.33
  other vias: 110.17,48.76
N$X.2895  (via drill 0.2)  (1 unrouted)
  Bottom 0.2: 111.99,48.76 111.44,49.31 111.09,49.31
  other vias: 111.94,48.74
N$X.2896  (via drill 0.2)  (1 unrouted)
  Bottom 0.2: 5.34,59.42 4.8,59.96 4.45,59.96
  other vias: 5.3,59.4
N$X.2897  (via drill 0.2)  (1 unrouted)
  Bottom 0.2: 7.14,59.42 6.59,59.96 6.25,59.96
  other vias: 7.09,59.4
N$X.2898  (via drill 0.2)  (1 unrouted)
  Bottom 0.2: 8.87,59.44 8.33,59.98 7.97,59.98
  other vias: 8.83,59.42
N$X.2899  (via drill 0.2)  (1 unrouted)
  Bottom 0.2: 10.56,59.4 10.01,59.94 9.66,59.94
  other vias: 10.51,59.38
N$X.2900  (via drill 0.2)  (1 unrouted)
  Bottom 0.2: 12.37,59.44 11.83,59.98 11.48,59.98
  other vias: 12.33,59.42
N$X.2901  (via drill 0.2)  (1 unrouted)
  Bottom 0.2: 14.17,59.42 13.62,59.96 13.27,59.96
  other vias: 14.12,59.4
N$X.2902  (via drill 0.2)  (1 unrouted)
  Bottom 0.2: 15.92,59.4 15.37,59.94 15.02,59.94
  other vias: 16.05,59.35
N$X.2903  (via drill 0.2)  (1 unrouted)
  Bottom 0.2: 17.69,59.4 17.14,59.94 16.79,59.94
  other vias: 17.8,59.35
N$X.2904  (via drill 0.2)  (1 unrouted)
  Bottom 0.2: 19.44,59.46 18.89,60.01 18.54,60.01
  other vias: 19.6,59.36
N$X.2905  (via drill 0.2)  (1 unrouted)
  Bottom 0.2: 19.63,61.94 18.89,62.54 18.54,62.54
  other vias: 19.63,61.88
N$X.2906  (via drill 0.2)  (1 unrouted)
  Bottom 0.2: 17.69,62 17.14,62.54 16.79,62.54
  other vias: 17.8,61.89
N$X.2907  (via drill 0.2)  (1 unrouted)
  Bottom 0.2: 15.83,62 15.29,62.54 14.94,62.54
  other vias: 16.01,61.9
N$X.2908  (via drill 0.2)  (1 unrouted)
  Bottom 0.2: 14.15,61.98 13.6,62.52 13.25,62.52
  other vias: 14.12,61.92
N$X.2909  (via drill 0.2)  (1 unrouted)
  Bottom 0.2: 12.31,61.98 11.76,62.52 11.41,62.52
  other vias: 12.28,61.94
N$X.2910  (via drill 0.2)  (1 unrouted)
  Bottom 0.2: 10.49,61.96 9.95,62.5 9.6,62.5
  other vias: 10.55,61.94
N$X.2911  (via drill 0.2)  (1 unrouted)
  Bottom 0.2: 8.76,61.96 8.21,62.5 7.86,62.5
  other vias: 8.78,61.89
N$X.2912  (via drill 0.2)  (1 unrouted)
  Bottom 0.2: 6.94,62 6.4,62.54 6.05,62.54
  other vias: 7.04,61.89
N$X.2913  (via drill 0.2)  (1 unrouted)
  Bottom 0.2: 5.24,62 4.69,62.54 4.34,62.54
  other vias: 5.26,61.89
N$X.2914  (via drill 0.2)  (1 unrouted)
  Bottom 0.2: 3.42,62.04 2.88,62.59 2.53,62.59
  other vias: 3.48,61.92
N$X.2915  (via drill 0.2)  (1 unrouted)
  Bottom 0.2: 3.51,64.65 2.97,65.19 2.62,65.19
  other vias: 3.47,64.63
N$X.2916  (via drill 0.2)  (1 unrouted)
  Bottom 0.2: 5.28,64.65 4.73,65.19 4.38,65.19
  other vias: 5.23,64.63
N$X.2917  (via drill 0.2)  (1 unrouted)
  Bottom 0.2: 7.1,64.6 6.55,65.15 6.21,65.15
  other vias: 7.05,64.58
N$X.2918  (via drill 0.2)  (1 unrouted)
  Bottom 0.2: 8.92,64.6 8.37,65.15 8.02,65.15
  other vias: 8.87,64.58
N$X.2919  (via drill 0.2)  (1 unrouted)
  Bottom 0.2: 10.6,64.6 10.06,65.15 9.71,65.15
  other vias: 10.6,64.58
N$X.2920  (via drill 0.2)  (1 unrouted)
  Bottom 0.2: 12.35,64.65 11.81,65.19 11.46,65.19
  other vias: 12.31,64.54
N$X.2921  (via drill 0.2)  (1 unrouted)
  Bottom 0.2: 14.06,64.67 13.51,65.21 13.16,65.21
  other vias: 14.09,64.56
N$X.2922  (via drill 0.2)  (1 unrouted)
  Bottom 0.2: 15.83,64.69 15.29,65.24 14.94,65.24
  other vias: 16.02,64.55
N$X.2923  (via drill 0.2)  (1 unrouted)
  Bottom 0.2: 17.67,64.67 17.12,65.21 16.77,65.21
  other vias: 17.77,64.57
N$X.2924  (via drill 0.2)  (1 unrouted)
  Bottom 0.2: 19.36,64.67 18.81,65.21 18.46,65.21
  other vias: 19.55,64.55
N$X.2925  (via drill 0.2)  (1 unrouted)
  Bottom 0.2: 3.53,67.32 2.99,67.86 2.64,67.86
  other vias: 3.46,67.19
N$X.2926  (via drill 0.2)  (1 unrouted)
  Bottom 0.2: 5.28,67.32 4.73,67.86 4.38,67.86
  other vias: 5.23,67.21
N$X.2927  (via drill 0.2)  (1 unrouted)
  Bottom 0.2: 7.05,67.25 6.51,67.8 6.16,67.8
  other vias: 7.07,67.19
N$X.2928  (via drill 0.2)  (1 unrouted)
  Bottom 0.2: 8.81,67.27 8.26,67.82 7.91,67.82
  other vias: 8.78,67.17
N$X.2929  (via drill 0.2)  (1 unrouted)
  Bottom 0.2: 10.56,67.25 10.01,67.8 9.66,67.8
  other vias: 10.57,67.17
N$X.2930  (via drill 0.2)  (1 unrouted)
  Bottom 0.2: 12.33,67.27 11.79,67.82 11.44,67.82
  other vias: 12.35,67.19
N$X.2931  (via drill 0.2)  (1 unrouted)
  Bottom 0.2: 14.06,67.27 13.51,67.82 13.16,67.82
  other vias: 14.07,67.21
N$X.2932  (via drill 0.2)  (1 unrouted)
  Bottom 0.2: 15.88,67.3 15.33,67.84 14.98,67.84
  other vias: 15.98,67.18
N$X.2933  (via drill 0.2)  (1 unrouted)
  Bottom 0.2: 17.69,67.25 17.14,67.8 16.79,67.8
  other vias: 17.78,67.16
N$X.2934  (via drill 0.2)  (1 unrouted)
  Bottom 0.2: 19.53,67.27 18.98,67.82 18.63,67.82
  other vias: 19.61,67.14
N$X.2935  (via drill 0.2)  (1 unrouted)
  Bottom 0.2: 19.38,69.88 18.83,70.42 18.48,70.42
  other vias: 19.33,69.86
N$X.2936  (via drill 0.2)  (1 unrouted)
  Bottom 0.2: 17.56,69.88 17.02,70.42 16.66,70.42
  other vias: 17.6,69.8
N$X.2937  (via drill 0.2)  (1 unrouted)
  Bottom 0.2: 15.88,69.88 15.33,70.42 14.98,70.42
  other vias: 15.83,69.86
N$X.2938  (via drill 0.2)  (1 unrouted)
  Bottom 0.2: 14.1,69.9 13.56,70.44 13.21,70.44
  other vias: 14.06,69.88
N$X.2939  (via drill 0.2)  (1 unrouted)
  Bottom 0.2: 12.35,69.81 11.81,70.36 11.46,70.36
  other vias: 12.31,69.79
N$X.2940  (via drill 0.2)  (1 unrouted)
  Bottom 0.2: 10.6,69.81 10.06,70.36 9.71,70.36
  other vias: 10.56,69.79
N$X.2941  (via drill 0.2)  (1 unrouted)
  Bottom 0.2: 8.81,69.86 8.26,70.4 7.91,70.4
  other vias: 8.76,69.84
N$X.2942  (via drill 0.2)  (1 unrouted)
  Bottom 0.2: 7.08,69.94 6.53,70.49 6.18,70.49
  other vias: 7.05,69.84
N$X.2943  (via drill 0.2)  (1 unrouted)
  Bottom 0.2: 5.34,69.88 4.8,70.42 4.45,70.42
  other vias: 5.3,69.86
N$X.2944  (via drill 0.2)  (1 unrouted)
  Bottom 0.2: 3.47,69.88 2.92,70.42 2.57,70.42
  other vias: 3.42,69.86
N$X.2945  (via drill 0.2)  (1 unrouted)
  Bottom 0.2: 21.23,72.39 20.69,72.94 20.34,72.94
  other vias: 21.19,72.37
N$X.2946  (via drill 0.2)  (1 unrouted)
  Bottom 0.2: 21.21,69.83 20.67,70.38 20.32,70.38
  other vias: 21.17,69.81
N$X.2947  (via drill 0.2)  (1 unrouted)
  Bottom 0.2: 21.17,67.19 20.62,67.73 20.27,67.73
  other vias: 21.33,67.17
N$X.2948  (via drill 0.2)  (1 unrouted)
  Bottom 0.2: 21.19,64.6 20.64,65.15 20.29,65.15
  other vias: 21.39,64.54
N$X.2949  (via drill 0.2)  (1 unrouted)
  Bottom 0.2: 21.19,61.96 20.64,62.5 20.29,62.5
  other vias: 21.39,61.89
N$X.2950  (via drill 0.2)  (1 unrouted)
  Bottom 0.2: 23.17,61.92 22.42,62.5 22.07,62.5
  other vias: 23.2,61.91
N$X.2951  (via drill 0.2)  (1 unrouted)
  Bottom 0.2: 23.29,64.55 22.46,65.15 22.11,65.15
  other vias: 23.31,64.52
N$X.2952  (via drill 0.2)  (1 unrouted)
  Bottom 0.2: 22.98,67.25 22.44,67.8 22.09,67.8
  other vias: 23.08,67.17
N$X.2953  (via drill 0.2)  (1 unrouted)
  Bottom 0.2: 22.98,69.9 22.44,70.44 22.09,70.44
  other vias: 23.25,69.81
N$X.2954  (via drill 0.2)  (1 unrouted)
  Bottom 0.2: 23.19,72.38 22.46,72.98 22.11,72.98
  other vias: 23.2,72.38
N$X.2955  (via drill 0.2)  (1 unrouted)
  Bottom 0.2: 24.97,72.38 24.43,72.93 23.84,72.98
  other vias: 25.01,72.37
N$X.2956  (via drill 0.2)  (1 unrouted)
  Bottom 0.2: v25.03,69.77 24.19,70.44 23.84,70.44
N$X.2957  (via drill 0.2)  (1 unrouted)
  Bottom 0.2: 24.97,67.22 24.17,67.82 23.82,67.82
  other vias: 25.02,67.18
N$X.2958  (via drill 0.2)  (1 unrouted)
  Bottom 0.2: 24.94,64.57 24.39,65.12 23.84,65.08
  other vias: 24.95,64.59
N$X.2959  (via drill 0.2)  (1 unrouted)
  Bottom 0.2: 25.02,61.93 24.47,62.48 23.91,62.48
  other vias: 25.01,61.91
N$X.2960  (via drill 0.2)  (1 unrouted)
  Bottom 0.2: 26.76,61.92 26.22,62.47 25.5,62.5
  other vias: 26.78,61.92
N$X.2961  (via drill 0.2)  (1 unrouted)
  Bottom 0.2: 26.74,64.59 26.2,65.13 25.46,65.19
  other vias: 26.77,64.56
N$X.2962  (via drill 0.2)  (1 unrouted)
  Bottom 0.2: 26.82,67.19 26.27,67.74 25.55,67.86
  other vias: 26.8,67.16
N$X.2963  (via drill 0.2)  (1 unrouted)
  Bottom 0.2: 26.74,69.86 25.83,70.53 25.48,70.53
  other vias: 26.81,69.81
N$X.2964  (via drill 0.2)  (1 unrouted)
  Bottom 0.2: v26.82,72.44 25.81,73.03 25.46,73.03
N$X.2965  (via drill 0.2)  (1 unrouted)
  Bottom 0.2: 28.55,72.43 28,72.97 27.23,73.03
  other vias: 28.56,72.4
N$X.2966  (via drill 0.2)  (1 unrouted)
  Bottom 0.2: 28.62,69.83 27.61,70.47 27.25,70.47
  other vias: 28.61,69.82
N$X.2967  (via drill 0.2)  (1 unrouted)
  Bottom 0.2: 28.54,67.2 27.65,67.8 27.3,67.8
  other vias: 28.6,67.19
N$X.2968  (via drill 0.2)  (1 unrouted)
  Bottom 0.2: 28.53,64.59 27.63,65.19 27.28,65.19
  other vias: 28.56,64.57
N$X.2969  (via drill 0.2)  (1 unrouted)
  Bottom 0.2: 28.56,61.93 27.63,62.5 27.28,62.5
  other vias: 28.57,61.95
N$X.2970  (via drill 0.2)  (1 unrouted)
  Bottom 0.2: 30.36,61.95 29.82,62.5 29.11,62.54
  other vias: 30.41,61.94
N$X.2971  (via drill 0.2)  (1 unrouted)
  Bottom 0.2: 30.34,64.58 29.45,65.17 29.09,65.17
  other vias: 30.41,64.57
N$X.2972  (via drill 0.2)  (1 unrouted)
  Bottom 0.2: 30.52,67.08 29.97,67.62 29.14,67.69
  other vias: 30.39,67.18
N$X.2973  (via drill 0.2)  (1 unrouted)
  Bottom 0.2: 30.36,69.9 29.82,70.44 29.03,70.42
  other vias: 30.38,69.79
N$X.2974  (via drill 0.2)  (1 unrouted)
  Bottom 0.2: 30.25,72.46 29.36,73 29,73
  other vias: 30.34,72.39
N$X.2975  (via drill 0.2)  (1 unrouted)
  Bottom 0.2: 32.27,72.44 31.72,72.98 31.24,73.05
  other vias: 32.2,72.44
N$X.2976  (via drill 0.2)  (1 unrouted)
  Bottom 0.2: 32.18,69.9 31.61,70.4 31.18,70.45
  other vias: 32.22,69.84
N$X.2977  (via drill 0.2)  (1 unrouted)
  Bottom 0.2: 32.24,67.19 31.7,67.73 31.09,67.82
  other vias: 32.2,67.19
N$X.2978  (via drill 0.2)  (1 unrouted)
  Bottom 0.2: 32.11,64.67 31.11,65.24 30.75,65.24
  other vias: 32.2,64.59
N$X.2979  (via drill 0.2)  (1 unrouted)
  Bottom 0.2: 32.18,61.91 31.13,62.54 30.78,62.54
  other vias: 32.2,61.89
N$X.2980  (via drill 0.2)  (1 unrouted)
  Bottom 0.2: 34.06,61.95 33.52,62.5 32.9,62.52
  other vias: 34.06,61.91
N$X.2981  (via drill 0.2)  (1 unrouted)
  Bottom 0.2: 33.93,64.63 33.21,65.22 32.86,65.22
  other vias: 34.06,64.59
N$X.2982  (via drill 0.2)  (1 unrouted)
  Bottom 0.2: 34.02,67.23 33.48,67.77 33.02,67.75
  other vias: 34,67.16
N$X.2983  (via drill 0.2)  (1 unrouted)
  Bottom 0.2: 33.91,69.92 33.36,70.47 32.82,70.42
  other vias: 33.95,69.81
N$X.2984  (via drill 0.2)  (1 unrouted)
  Bottom 0.2: 33.97,72.46 33.43,73 33.08,73
  other vias: 33.99,72.39
N$X.2985  (via drill 0.2)  (1 unrouted)
  Bottom 0.2: 35.77,72.44 35.22,72.98 35.02,72.92
  other vias: 35.79,72.42
N$X.2986  (via drill 0.2)  (1 unrouted)
  Bottom 0.2: 35.81,69.9 35.27,70.44 34.85,70.44
  other vias: 35.8,69.79
N$X.2987  (via drill 0.2)  (1 unrouted)
  Bottom 0.2: 35.79,67.16 35.25,67.71 34.7,67.79
  other vias: 35.81,67.19
N$X.2988  (via drill 0.2)  (1 unrouted)
  Bottom 0.2: 35.75,64.67 35.2,65.22 34.63,65.22
  other vias: 35.81,64.59
N$X.2989  (via drill 0.2)  (1 unrouted)
  Bottom 0.2: 35.79,62 35.25,62.54 34.72,62.56
  other vias: 35.81,61.93
N$X.2990  (via drill 0.2)  (1 unrouted)
  Bottom 0.2: 37.47,62.02 37.3,62.55 36.47,62.55
  other vias: 37.59,61.94
N$X.2991  (via drill 0.2)  (1 unrouted)
  Bottom 0.2: 37.6,64.6 37.06,65.15 36.6,65.17
  other vias: 37.6,64.58
N$X.2992  (via drill 0.2)  (1 unrouted)
  Bottom 0.2: v37.6,67.18 37.06,67.73 36.58,67.79
N$X.2993  (via drill 0.2)  (1 unrouted)
  Bottom 0.2: v37.65,69.83 37.1,70.38 36.73,70.46
N$X.2994  (via drill 0.2)  (1 unrouted)
  Bottom 0.2: 37.65,72.44 37.1,72.98 36.62,72.96
  other vias: 37.63,72.42
N$X.2995  (via drill 0.2)  (1 unrouted)
  Bottom 0.2: 39.47,72.39 38.92,72.94 38.38,73
  other vias: 39.45,72.39
N$X.2996  (via drill 0.2)  (1 unrouted)
  Bottom 0.2: 39.4,69.88 38.86,70.42 38.22,70.44
  other vias: 39.42,69.83
N$X.2997  (via drill 0.2)  (1 unrouted)
  Bottom 0.2: 39.38,67.27 38.83,67.82 38.29,67.82
  other vias: 39.44,67.19
N$X.2998  (via drill 0.2)  (1 unrouted)
  Bottom 0.2: v39.44,64.58 38.9,65.13 38.28,65.15
N$X.2999  (via drill 0.2)  (1 unrouted)
  Bottom 0.2: 39.36,61.95 38.81,62.5 38.38,62.5
  other vias: 39.4,61.95
N$X.3011  (via drill 0.2)  (1 unrouted)
  Bottom 0.2: 76.78,19.97 76.24,20.51 75.89,20.51
  other vias: 76.74,19.95
N$X.3069  (via drill 0.2)  (1 unrouted)
  Bottom 0.2: 66.62,75 66.08,75.54 65.72,75.54
  other vias: 66.58,74.98
N$X.3070  (via drill 0.2)  (1 unrouted)
  Bottom 0.2: 66.53,72.48 65.99,73.03 65.64,73.03
  other vias: 66.49,72.46
N$X.3071  (via drill 0.2)  (1 unrouted)
  Bottom 0.2: 68.28,75.08 67.73,75.63 67.38,75.63
  other vias: 68.23,75.06
N$X.3072  (via drill 0.2)  (1 unrouted)
  Bottom 0.2: 70.12,75 69.58,75.54 69.23,75.54
  other vias: 70.08,74.98
N$X.3073  (via drill 0.2)  (1 unrouted)
  Bottom 0.2: 71.92,75.02 71.38,75.57 71.03,75.57
  other vias: 71.88,75
N$X.3074  (via drill 0.2)  (1 unrouted)
  Bottom 0.2: 73.55,75.02 73,75.57 72.66,75.57
  other vias: 73.5,75
N$X.3075  (via drill 0.2)  (1 unrouted)
  Bottom 0.2: 75.51,75.02 74.97,75.57 74.61,75.57
  other vias: 75.36,74.98
N$X.3076  (via drill 0.2)  (1 unrouted)
  Bottom 0.2: 77.11,75.08 76.56,75.63 76.22,75.63
  other vias: 77.06,75.06
N$X.3077  (via drill 0.2)  (1 unrouted)
  Bottom 0.2: 78.82,75.05 78.28,75.6 77.92,75.6
  other vias: 78.78,75.03
N$X.3078  (via drill 0.2)  (1 unrouted)
  Bottom 0.2: 80.7,75.08 80.16,75.63 79.8,75.63
  other vias: 80.66,74.98
N$X.3079  (via drill 0.2)  (1 unrouted)
  Bottom 0.2: 82.47,75.11 81.92,75.65 81.57,75.65
  other vias: 82.4,74.98
N$X.3080  (via drill 0.2)  (1 unrouted)
  Bottom 0.2: 82.5,72.51 81.95,73.06 81.6,73.06
  other vias: 82.45,72.41
N$X.3081  (via drill 0.2)  (1 unrouted)
  Bottom 0.2: 80.61,72.4 80.07,72.95 79.72,72.95
  other vias: 80.63,72.4
N$X.3082  (via drill 0.2)  (1 unrouted)
  Bottom 0.2: 78.91,72.4 78.36,72.95 78.01,72.95
  other vias: 78.86,72.38
N$X.3083  (via drill 0.2)  (1 unrouted)
  Bottom 0.2: 77.14,72.4 76.59,72.95 76.24,72.95
  other vias: 77.09,72.38
N$X.3084  (via drill 0.2)  (1 unrouted)
  Bottom 0.2: 75.4,72.43 74.86,72.97 74.5,72.97
  other vias: 75.36,72.41
N$X.3085  (via drill 0.2)  (1 unrouted)
  Bottom 0.2: 73.63,72.4 73.08,72.95 72.73,72.95
  other vias: 73.63,72.38
N$X.3086  (via drill 0.2)  (1 unrouted)
  Bottom 0.2: 71.94,72.35 71.4,72.89 71.05,72.89
  other vias: 71.92,72.39
N$X.3087  (via drill 0.2)  (1 unrouted)
  Bottom 0.2: 70.09,72.37 69.55,72.92 69.2,72.92
  other vias: 70.13,72.44
N$X.3088  (via drill 0.2)  (1 unrouted)
  Bottom 0.2: 68.33,72.51 67.78,73.06 67.44,73.06
  other vias: 68.28,72.49
N$X.3092  (via drill 0.2)  (1 unrouted)
  Bottom 0.2: 68.33,69.86 67.78,70.41 67.44,70.41
  other vias: 68.28,69.84
N$X.3093  (via drill 0.2)  (1 unrouted)
  Bottom 0.2: 70.15,69.89 69.61,70.43 69.25,70.43
  other vias: 70.11,69.87
N$X.3094  (via drill 0.2)  (1 unrouted)
  Bottom 0.2: 71.97,69.83 71.43,70.38 71.08,70.38
  other vias: 71.93,69.81
N$X.3095  (via drill 0.2)  (1 unrouted)
  Bottom 0.2: 73.63,69.89 73.08,70.43 72.73,70.43
  other vias: 73.61,69.81
N$X.3096  (via drill 0.2)  (1 unrouted)
  Bottom 0.2: 75.37,69.83 74.83,70.38 74.47,70.38
  other vias: 75.33,69.81
N$X.3097  (via drill 0.2)  (1 unrouted)
  Bottom 0.2: 77.19,69.81 76.65,70.35 76.3,70.35
  other vias: 77.15,69.79
N$X.3098  (via drill 0.2)  (1 unrouted)
  Bottom 0.2: 78.98,69.89 78.44,70.43 78.09,70.43
  other vias: 78.94,69.83
N$X.3099  (via drill 0.2)  (1 unrouted)
  Bottom 0.2: 80.72,69.83 80.18,70.38 79.83,70.38
  other vias: 80.68,69.81
N$X.3100  (via drill 0.2)  (1 unrouted)
  Bottom 0.2: 82.52,69.78 81.97,70.32 81.62,70.32
  other vias: 82.41,69.8
N$X.3101  (via drill 0.2)  (1 unrouted)
  Bottom 0.2: 82.47,67.21 81.92,67.76 81.57,67.76
  other vias: 82.42,67.19
N$X.3102  (via drill 0.2)  (1 unrouted)
  Bottom 0.2: 80.78,67.18 80.23,67.73 79.89,67.73
  other vias: 80.73,67.16
N$X.3103  (via drill 0.2)  (1 unrouted)
  Bottom 0.2: 78.96,67.18 78.41,67.73 78.06,67.73
  other vias: 78.91,67.16
N$X.3104  (via drill 0.2)  (1 unrouted)
  Bottom 0.2: 77.14,67.21 76.59,67.76 76.24,67.76
  other vias: 77.09,67.19
N$X.3105  (via drill 0.2)  (1 unrouted)
  Bottom 0.2: 75.42,67.18 74.88,67.73 74.53,67.73
  other vias: 75.38,67.16
N$X.3106  (via drill 0.2)  (1 unrouted)
  Bottom 0.2: 73.63,67.18 73.08,67.73 72.73,67.73
  other vias: 73.63,67.2
N$X.3107  (via drill 0.2)  (1 unrouted)
  Bottom 0.2: 71.89,67.18 71.34,67.73 71,67.73
  other vias: 71.84,67.16
N$X.3108  (via drill 0.2)  (1 unrouted)
  Bottom 0.2: v70.09,67.18 69.55,67.73 69.2,67.73
N$X.3109  (via drill 0.2)  (1 unrouted)
  Bottom 0.2: 68.36,67.18 67.81,67.73 67.46,67.73
  other vias: 68.33,67.2
N$X.3116  (via drill 0.2)  (1 unrouted)
  Bottom 0.2: 68.44,64.62 67.89,65.16 67.55,65.16
  other vias: 68.39,64.6
N$X.3117  (via drill 0.2)  (1 unrouted)
  Bottom 0.2: 70.15,64.62 69.61,65.16 69.25,65.16
  other vias: 70.11,64.6
N$X.3118  (via drill 0.2)  (1 unrouted)
  Bottom 0.2: 71.92,64.64 71.38,65.19 71.03,65.19
  other vias: 71.88,64.62
N$X.3119  (via drill 0.2)  (1 unrouted)
  Bottom 0.2: 73.69,64.59 73.14,65.13 72.79,65.13
  other vias: 73.64,64.57
N$X.3120  (via drill 0.2)  (1 unrouted)
  Bottom 0.2: 75.4,64.56 74.86,65.1 74.5,65.1
  other vias: 75.36,64.54
N$X.3121  (via drill 0.2)  (1 unrouted)
  Bottom 0.2: 77.19,64.59 76.65,65.13 76.3,65.13
  other vias: 77.15,64.57
N$X.3122
  Bottom 0.2: 77.19,64.59 76.65,65.13 76.3,65.13
N$X.3123  (via drill 0.2)  (1 unrouted)
  Bottom 0.2: 79.04,64.59 78.5,65.13 78.14,65.13
  other vias: 79,64.57
N$X.3124  (via drill 0.2)  (1 unrouted)
  Bottom 0.2: 80.72,64.59 80.18,65.13 79.83,65.13
  other vias: 80.68,64.57
N$X.3125  (via drill 0.2)  (1 unrouted)
  Bottom 0.2: 82.5,64.56 81.95,65.1 81.6,65.1
  other vias: 82.45,64.54
N$X.3126  (via drill 0.2)  (1 unrouted)
  Bottom 0.2: 82.5,61.94 81.95,62.48 81.6,62.48
  other vias: 82.45,61.92
N$X.3127  (via drill 0.2)  (1 unrouted)
  Bottom 0.2: 80.7,62.02 80.16,62.56 79.8,62.56
  other vias: 80.66,62
N$X.3128  (via drill 0.2)  (1 unrouted)
  Bottom 0.2: 78.91,61.99 78.36,62.54 78.01,62.54
  other vias: 78.86,61.97
N$X.3129  (via drill 0.2)  (1 unrouted)
  Bottom 0.2: 77.03,62.07 76.48,62.62 76.13,62.62
  other vias: 77.15,61.93
N$X.3130  (via drill 0.2)  (1 unrouted)
  Bottom 0.2: 75.28,61.94 74.74,62.48 74.39,62.48
  other vias: 75.39,61.92
N$X.3131  (via drill 0.2)  (1 unrouted)
  Bottom 0.2: 73.63,61.96 73.08,62.51 72.73,62.51
  other vias: 73.58,61.94
N$X.3132  (via drill 0.2)  (1 unrouted)
  Bottom 0.2: 71.86,61.94 71.32,62.48 70.97,62.48
  other vias: 71.82,61.92
N$X.3133  (via drill 0.2)  (1 unrouted)
  Bottom 0.2: 70.15,61.96 69.61,62.51 69.25,62.51
  other vias: 70.11,61.94
N$X.3134  (via drill 0.2)  (1 unrouted)
  Bottom 0.2: 68.36,61.88 67.81,62.43 67.46,62.43
  other vias: 68.31,61.92
N$X.3135
  Bottom 0.2: 66.05,62.51 65.69,62.51
N$X.3138  (via drill 0.2)  (1 unrouted)
  Bottom 0.2: 84.29,75.05 83.75,75.6 83.39,75.6
  other vias: 84.18,74.97
N$X.3139  (via drill 0.2)  (1 unrouted)
  Bottom 0.2: 85.97,74.94 85.43,75.49 85.08,75.49
  other vias: 85.91,74.96
N$X.3140  (via drill 0.2)  (1 unrouted)
  Bottom 0.2: 87.74,75.02 87.19,75.57 86.84,75.57
  other vias: 87.69,75
N$X.3141  (via drill 0.2)  (1 unrouted)
  Bottom 0.2: 89.5,75.05 88.96,75.6 88.61,75.6
  other vias: 89.4,74.99
N$X.3142  (via drill 0.2)  (1 unrouted)
  Bottom 0.2: 91.22,75.05 90.67,75.6 90.33,75.6
  other vias: 91.17,75.03
N$X.3143  (via drill 0.2)  (1 unrouted)
  Bottom 0.2: 92.93,75.05 92.39,75.6 92.03,75.6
